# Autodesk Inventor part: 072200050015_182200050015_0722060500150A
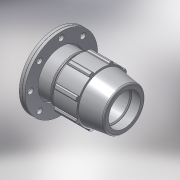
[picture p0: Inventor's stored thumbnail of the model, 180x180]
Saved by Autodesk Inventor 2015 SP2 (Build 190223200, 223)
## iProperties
Created: 2017-02
Part Number: 072200050015_182200050015_0722060500150A
Material: PVC-Piping
Description: PLASSON COMPRESSION FLANGE ADAPTOR 50-1.1/2"
Document SubType Name: Modeling
Designer: KIM
Mass: 92.6774 g
Surface Area: 199.44 cm^2
Volume: 66.1981 cm^3
Density: 1.4 g/cm^3
Appearance: Smooth - White
Author: KIM
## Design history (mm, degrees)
derived "07220.ipt"
feature "Solid1::07220.ipt"
tag "TaggingFeature1"
body "Solid1"
other parameters: "d4" = 18.28571, "d5" = 40.96, "d7" = 96, "d9" = 18.28571, "d11" = 3.65714, "d12" = 76.8, "d13" = 120 deg, "d14" = 65, "d15" = 12 deg, "d18" = 2.5, "d19" = 35 deg, "d20" = 17.5 deg, "d21" = 89.28, "d23" = 0, "d25" = 360 deg, "d27" = 1.92, "d42" = 44.8, "d43" = 2.88, "d46" = 1.5, "d53" = 1, "d67" = 4.8, "d68" = 93, "d70" = 128, "d73" = 10.66667, "d74" = 90 deg, "d75" = 0.3, "d77" = 18, "d78" = 55, "d80" = 0, "d82" = 360 deg, "d85" = 81.6, "d86" = 76.8, "d87" = 0.75, "d93" = 6.4, "d95" = 45, "d96" = 0.3, "d99" = 360 deg, "E_" = 96, "H_" = 128, "l_" = 93, "S_" = 18
